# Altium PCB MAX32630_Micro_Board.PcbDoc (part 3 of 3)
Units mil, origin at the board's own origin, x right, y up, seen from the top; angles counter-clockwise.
Board outline 1192.91 x 1079.23 mil, 6 copper layers (Top Layer, Ground Plane +, Mid-Layer 2, Mid-Layer 3, Power Plane 1.8v, Bottom Layer), stack 51.6 mil thick; 105 components, 122 nets, 1109 pads, 512 vias.
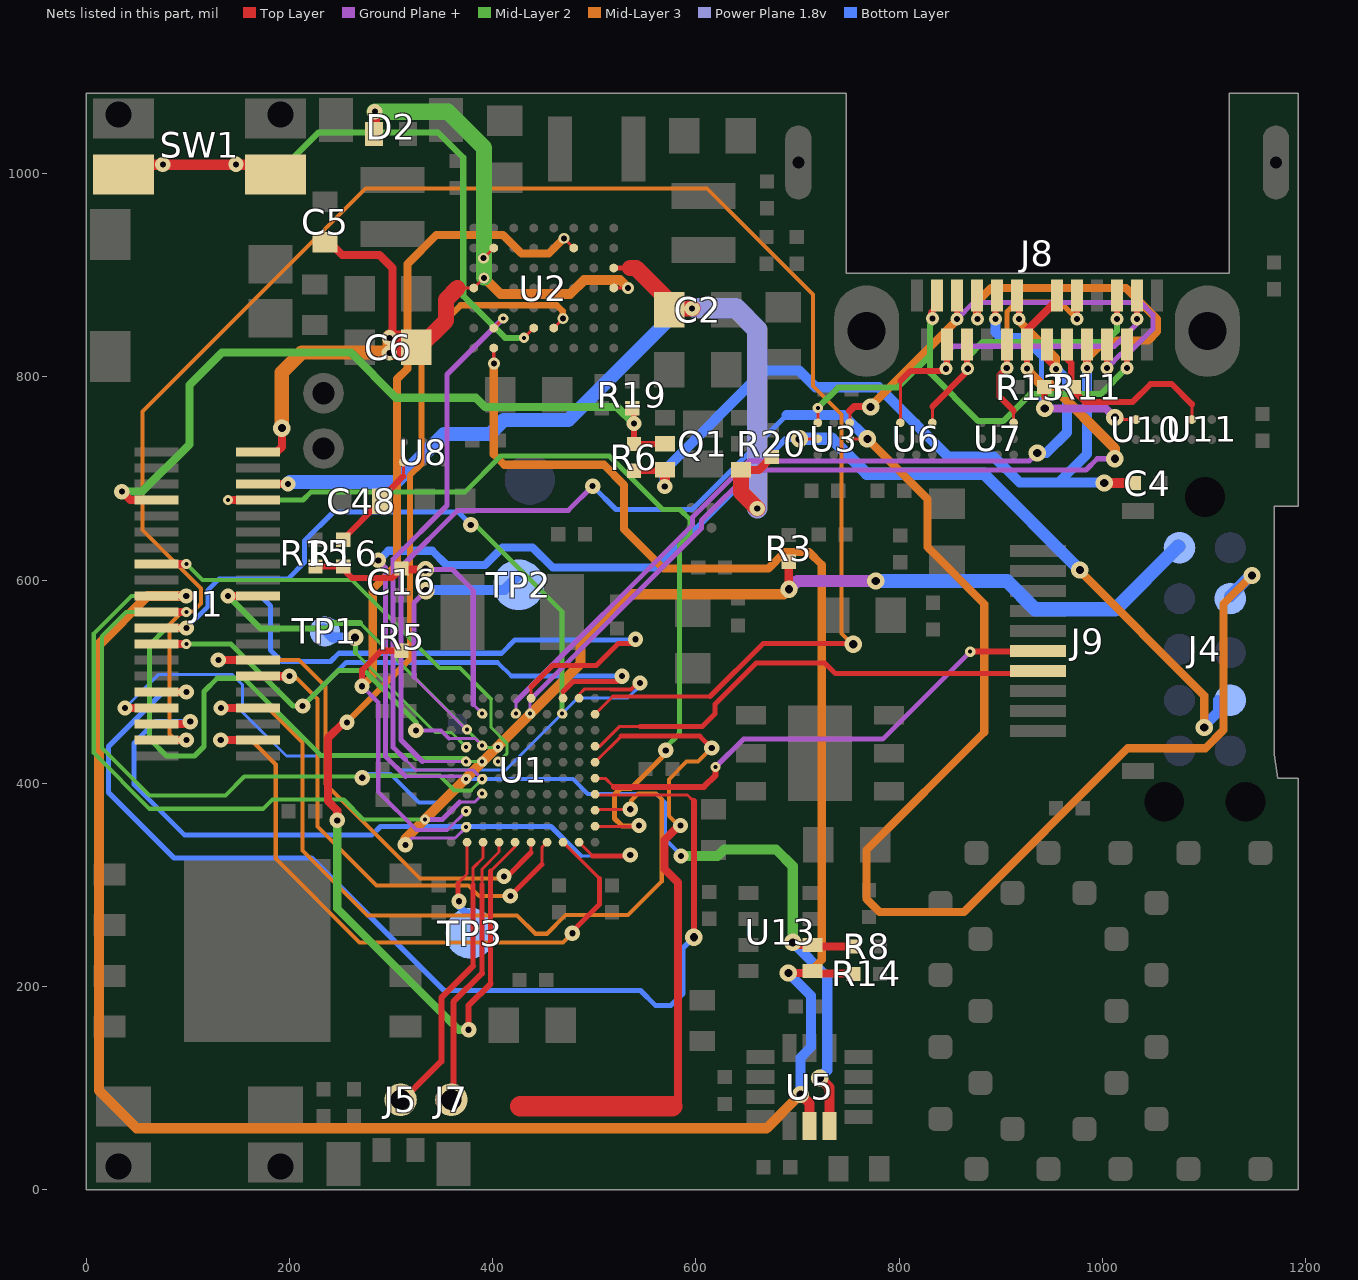
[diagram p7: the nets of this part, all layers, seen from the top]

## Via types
v1: diameter 15, hole 6, Top Layer to Bottom Layer, tented both sides, 180 vias
v2: diameter 10, hole 4, Top Layer to Ground Plane +, tented both sides, 134 vias
v3: diameter 17, hole 8, Top Layer to Bottom Layer, tented both sides, 82 vias
v4: diameter 10, hole 4, Ground Plane + to Mid-Layer 2, tented both sides, 57 vias
v5: diameter 12.8, hole 6, Top Layer to Bottom Layer, tented both sides, 20 vias
v6: diameter 10, hole 4, Top Layer to Ground Plane +, tented top, 16 vias
v7: diameter 10.63, hole 5.91, Top Layer to Bottom Layer, tented both sides, 13 vias
v8: diameter 10, hole 4, Ground Plane + to Mid-Layer 2, 5 vias
v9: diameter 11.81, hole 5.91, Top Layer to Bottom Layer, tented both sides, 3 vias
v10: diameter 14.17, hole 6, Top Layer to Bottom Layer, tented both sides, 1 vias
v11: diameter 14, hole 8, Top Layer to Bottom Layer, tented both sides, 1 vias

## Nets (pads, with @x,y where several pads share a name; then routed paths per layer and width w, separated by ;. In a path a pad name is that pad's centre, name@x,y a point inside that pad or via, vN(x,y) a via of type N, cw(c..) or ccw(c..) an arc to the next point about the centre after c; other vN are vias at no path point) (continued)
P53_SSEL: J1.19 pad.1@405.38,435.51 U1.D7 U1.F10 | length 962.9
  Top Layer w3: U1.F10@437.76,483.65 437.76,494.76 ; v1(540.49,541.74) 542.26,541.74 v1@543,541
  Top Layer w5: 437.76,494.76 459,516 502,516 523.39,537.39 537.39,537.39 540.49,540.49 v1(540.49,541.74)
  Top Layer w8: v1(139.54,584.27) J1.19@169,584.27
  Mid-Layer 2 w3: 269.26,557.89 392.15,435 403.08,435 v4@405.38,437.29
  Mid-Layer 2 w6: v1(139.54,584.27) 171.41,552.39 237.92,552.39 243.42,557.89 269.26,557.89
  Bottom Layer w5: v1(139.54,584.27) 171.73,584.27 181.39,574.61 181.39,530.98 192.48,519.89 240.44,519.89 248.56,528 408.83,528 421.83,541 v1@542,541
  other v2: 405.38,435.51
  other v4: 405.38,435.51
P54_SDIO2: J1.26 U1.C7 U1.H10 | length 803.8
  Top Layer w3: U1.H10@469.25,483.65 469.25,490.25 ; v1@525,502 v1@525,507
  Top Layer w5: 469.25,490.25 479,500 523,500 v1@525,502
  Top Layer w8: J1.26@69,537.02 v4(98.46,537.02)
  Ground Plane + w3: 356.87,444.13 382.8,444.13 v2(389.63,437.29)
  Ground Plane + w4: v1@326.9,452 349,452 356.87,444.13
  Ground Plane + w6: v1@325,453.9 v1@326.9,452
  Mid-Layer 2 w5: v4@98.89,536.89 142.5,536.89 203.39,476 v1(213,476) 248,511 273.5,511 325.05,459.45 v1@325.05,453.95
  Bottom Layer w4: 404.96,519 418.57,505.39
  Bottom Layer w5: v1(213,476) 256,519 404.96,519 ; 418.57,505.39 v1(527.39,505.39)
  other v1: 324.39,451.89
  other v2: 98.46,537.02
P55_SDIO3: J1.24 U1.C6 U1.H9 | length 1182.2
  Top Layer w8: J1.24@69,552.77 v1(98.46,552.77)
  Mid-Layer 2 w3: 373.59,424.39 376.43,421.54 v4(389.63,421.54) ; v1(378.39,654.39) 380.39,654.39 381.39,653.39 v1@380,652
  Mid-Layer 2 w5: v1(98.46,552.77) 78.77,552.77 62.39,536.39 62.39,443.39 78.89,426.89 106.5,426.89 115.89,436.28 115.89,490.39 128.89,503.39 154.89,503.39 230.78,427.5 321.28,427.5 324.39,424.39 373.59,424.39 ; v1(378.39,654.39) 382.89,654.39 468.37,568.91 v2(468.37,468.79)
  Bottom Layer w5: v1(98.46,552.77) 119.95,574.26 119.95,590.37 130.48,600.89 198.21,600.89 214.65,617.33 214.65,638.4 243.26,667 366,667 378.61,654.39 v1(378.39,654.39)
  other v2: 389.63,421.54
  other v4: 468.37,468.79
P56_SRN: J1.16 U1.D6 | length 456.6
  Top Layer w8: J1.16@69,615.76 v8(98.46,615.76)
  Mid-Layer 2 w3: 398.39,483.02 398.39,455.09 414,439.48 414,429 406.54,421.54 v4(405.38,421.54)
  Mid-Layer 2 w4: v8(98.46,615.76) 114.34,599.89 261.39,599.89 347.89,513.39 368.02,513.39 398.39,483.02
  other v2: 405.38,421.54
  other v6: 98.46,615.76
P57_SDA: J1.22 pad.1@389.63,404.02 R8.1 U1.C5 U2.B2 U5.14 U13.3 | length 2079
  Top Layer w3: U2.B2@401.07,848.07 v2@411.24,858.24 ; U13.3@715,240.96 U13.3@716.57,239.39 ; R8.1@753.39,239.39 R8.1@754.39,238.39
  Top Layer w8: J1.22@69,568.52 v4(98.46,568.52) ; v3@697.4,240.96 U13.3@715,240.96 ; U13.3@716.57,239.39 R8.1@753.39,239.39
  Top Layer w10: v3(722,110) 731.68,100.32 U5.14@731.68,62.61
  Ground Plane + w3: 314.11,423.39 325.11,412.39 ; 325.11,412.89 380.76,412.89 v2(389.63,404.02)
  Ground Plane + w5: 314.11,423.39 302.03,435.47 302.03,620.53 355,673.5 355,802.33 v2@411.07,858.41
  Mid-Layer 2 w3: 378.6,393 v2(389.63,404.02)
  Mid-Layer 2 w4: v4(98.46,568.52) 39.02,568.52 15.39,544.89 15.39,434.76 62.26,387.89 136.89,387.89 155.5,406.5 266.72,406.5 268.61,408.39 268.61,402.39 v1(271.61,405.39) 273.61,407.39 348.02,407.39 362.41,393 378.6,393
  Mid-Layer 2 w10: v1(585.39,328.39) 621.39,328.39 627.89,334.89 678.89,334.89 695.39,318.39 v3(695.39,243.39)
  Bottom Layer w4: v1@271.61,405.89 274.95,409.23 299.27,409.23 327.5,381 347,381 370.02,404.02 478.94,404.02 493.58,389.39 561.02,389.39 569.53,380.88 569.53,345.25 582.39,332.39 v1@582.39,328.39
  Bottom Layer w10: v3(695.39,243.39) 729.39,209.39 729.39,117.39 v3(722,110)
  other v2: 98.46,568.52 410.39,857.39
  other v4: 389.63,404.02
P60_SCL: J1.20 R14.1 U1.C4 U2.B1 U5.13 U13.4 | length 3111.9
  Top Layer w3: v9@401.07,813 U2.B1@401.07,828.39 ; U13.4@715,215.37 U13.4@717.02,217.39
  Top Layer w8: J1.20@69,584.27 v1@98.46,584.27 ; v3(691,213.18) U13.4@712.78,213.18 ; U13.4@716.57,212.82 R14.1@753.39,212.82
  Top Layer w10: v3(703,93.78) 712,84.78 U5.13@712,62.61
  Ground Plane + w3: 367.39,381.39 382.03,381.39 389.63,388.98 v2(389.63,390.05)
  Ground Plane + w5: v4(333.39,364.39) 350.39,364.39 367.39,381.39
  Mid-Layer 2 w4: v1(98.39,584.27) 44.38,584.27 7.39,547.28 7.39,429.89 62.39,374.89 174.11,374.89 183.22,384 253.43,384 273.04,364.39 v4(333.39,364.39)
  Mid-Layer 3 w8: v9@401.07,811.48 401.07,723.81 411.39,713.5 509.5,713.5 529.39,693.61 529.39,650 567.89,611.5 671.5,611.5 687.5,627.5 711.5,627.5 723.89,615.11 723.89,226.31 710.76,213.18 v3(691,213.18)
  Mid-Layer 3 w10: v1(98.39,584.27) 60.27,584.27 12.39,536.39 12.39,97.76 49.76,60.39 669.61,60.39 v3(703,93.78)
  Bottom Layer w10: v3(691,213.18) 713.39,190.79 713.39,140.39 703,130 v3(703,93.78)
  other v9: 401.39,813.39
P61_SPI_SCK: J1.34 U1.J10 | length 711.3
  Top Layer w3: U1.J10@485,483.65 485,487.38 490.62,493 516,493 516.61,492.39
  Top Layer w4: 516.61,492.39 536.34,492.39 v1@543.95,500
  Top Layer w8: v1(38.03,474.03) J1.34@69,474.03
  Bottom Layer w3: v1(38.03,474.03) 70.89,506.89 143.93,506.89 153.65,497.17 153.65,470.24 197.01,426.88 294.3,426.88 308.17,413.01 412.86,413.01 483.74,483.89 533,483.89 v1@546.66,497.55
  other v1: 544.89,498.81
P62_SPI_MOSI: J1.38 U1.K9 | length 1847.5
  Top Layer w3: U1.K9@500.75,467.91 518.23,485.39
  Top Layer w4: 518.23,485.39 614.02,485.39
  Top Layer w5: 614.02,485.39 666.02,537.39 752.89,537.39 v3@754.89,539.39
  Top Layer w8: J1.38@69,442.54 v1(98.46,442.54)
  Mid-Layer 3 w4: v1(98.46,442.54) 87.68,442.54 81.89,448.32 81.89,556.39 94.5,569 105,569 112.89,576.89 112.89,591.89 55.39,649.39 55.39,765.89 274.89,985.39 611,985.39 715.39,881 715.39,791 743.39,763 743.39,547.39 v3@754.39,536.39
  other v3: 754.89,536.89
P64_DISP_EXTCOM: J9.4 U1.K7 | length 473.2
  Top Layer w3: U1.K7@500.75,436.41 505.41,436.41 525,456 544.93,456 545.04,455.89
  Top Layer w5: 545.04,455.89 606.39,455.89 618.89,468.39 618.89,477.89 659.39,518.39 726.89,518.39 737.28,508 J9.4@930,508
P65_PUSHBTN: U1.K6 | length 671.2
  Top Layer w3: U1.K6@500.75,420.66 526.48,446.39
  Top Layer w5: 526.48,446.39 603.89,446.39 v1(615.59,434.69)
  Top Layer w8: 582.39,87.39 582.39,302.39 569,315.78 569,344 v1@585,360
  Top Layer w20: 427.2,81.95 576.8,81.95
  Mid-Layer 3 w3: v1@583,358.39 v1(585,358.39)
  Mid-Layer 3 w4: v1@583,358.39 573.39,368 573.39,403.89 590.89,421.39 602.29,421.39 v1(615.59,434.69)
P66_DISP_ON/O\F\F\: J9.5 U1.K5 | length 499.4
  Top Layer w3: U1.K5@500.75,404.91 510.86,404.91 519.39,396.39
  Top Layer w6: 519.39,396.39 607.89,396.39 619.39,407.89 v2(619.39,416) ; v2(870,529.5) J9.5@936.69,529.5
  Ground Plane + w5: v2(619.39,416) 646.78,443.39 783.89,443.39 v2(870,529.5)
P67_SDA: J1.32 U1.K4 | length 1124.3
  Top Layer w3: U1.K4@500.75,389.17 501.41,388.5 591.78,388.5 598,382.28
  Top Layer w6: v3(598,248.39) 598,382.28
  Top Layer w8: J1.32@69,489.78 v1(98.46,489.78)
  Bottom Layer w5: v1(98.46,489.78) 75.59,489.78 21.89,436.08 21.89,390.89 86.39,326.39 221.59,326.39 352.01,195.96 545.57,195.96 560.15,181.39 575.64,181.39 587.39,193.14 587.39,237.78 v3(598,248.39)
P70_SCL: J1.33 U1.K3 | length 811.1
  Top Layer w3: U1.K3@500.75,373.42 501.17,373 502.55,374.39 v1@536.39,374.39
  Top Layer w8: v1(132.53,474.03) J1.33@169,474.03
  Ground Plane + w4: v1@536.39,374.39 v1@540.57,374.39
  Mid-Layer 3 w4: v1(132.53,474.03) 178.97,474.03 213,440 213,333.89 277,269.89 424.11,269.89 442.11,251.89 453.39,251.89 471.89,270.39 533.39,270.39 566.39,303.39 566.39,384.39 560.89,389.89 543.28,389.89 536.39,383 v1@536.39,374.39
  other v1: 535.39,374.39
P71_SDA: J1.7 U1.K2 | length 927.8
  Top Layer w3: U1.K2@500.75,357.67 v1@543.95,357.67
  Top Layer w8: v4(139.54,678.76) J1.7@169,678.76
  Mid-Layer 2 w5: v4(139.54,678.76) 213.26,678.76 221,686.5 372.5,686.5 408,722 514.78,722 567.39,669.39 584.39,669.39 594.39,659.39 594.39,644.39 584,634 584,449 v1@569,434
  Mid-Layer 3 w5: v1(543.95,358.45) 543.58,358.08 527.2,358.08 519.89,365.39 519.89,388.89 525.89,394.89 535.96,394.89 569,427.93 v1@569,432.39
  other v1: 570.39,432.39
  other v2: 139.54,678.76
P72_SCL: J1.36 U1.J1 | length 718.4
  Top Layer w3: U1.J1@485,341.92 498.53,328.39 ; v1@532.86,328.39 v1@533.25,328
  Top Layer w5: 498.53,328.39 v1@532.86,328.39
  Top Layer w8: J1.36@69,458.28 100.04,458.28 v1(102.39,460.64)
  Bottom Layer w3: 486.54,328.46 v1@534.46,328.46
  Bottom Layer w5: v1(102.39,460.64) 68.14,460.64 46.81,439.31 46.81,398.97 96.89,348.89 280.97,348.89 289.55,357.47 457.53,357.47 486.54,328.46 ; v1@534.46,328.46 v1(535.39,329.39)
P73_SCK: J1.37 U1.H1 | length 640.3
  Top Layer w3: U1.H1@469.25,341.92 469.47,341.92 505,306.39 ; v1@480.4,251.99 v1@480.4,256.13
  Top Layer w5: v1@480.4,256.13 505,280.73 505,306.39
  Top Layer w8: v1(132.39,442.54) J1.37@169,442.54
  Mid-Layer 3 w4: v1(132.39,442.54) 162.39,442.54 186.5,418.42 186.5,326 269.11,243.39 469.39,243.39 v1@480,254
  other v1: 478.39,252.39
P74_MOSI: J1.29 U1.G1 | length 479.3
  Top Layer w3: 448.39,320 448.39,336.81 U1.G1@453.5,341.92
  Top Layer w5: v1(417.39,289) 448.39,320
  Top Layer w8: J1.29@169.14,505.39 v1(199.89,505.39)
  Mid-Layer 3 w4: v1(199.89,505.39) 205.11,505.39 227.39,483.11 227.39,357.61 285.61,299.39 376.39,299.39 386.78,289 v1(417.39,289)
P75_MISO: J1.27 U1.F1 | length 512.5
  Top Layer w3: v1@411,309 v1@415,309 ; 437.76,331.76 U1.F1@437.76,341.92
  Top Layer w5: v1@415,309 437.76,331.76
  Top Layer w8: v1(130,521.28) J1.27@169,521.28
  Ground Plane + w3: v1@410.39,308.39 v1@411,309
  Mid-Layer 3 w4: v1(130,521.28) 209.22,521.28 235.39,495.11 235.39,399.39 328.39,306.39 408.39,306.39 v1@410.39,308.39
  other v1: 411.04,308.39
P76_PMIC_PFN2: U1.E1 U2.E2 | length 1161.2
  Top Layer w3: 397.89,313.39 422.01,337.51 U1.E1@422.01,341.92 ; U2.E2@460.13,848.07 v7@470.3,858.24
  Top Layer w5: 397.89,202.89 397.89,313.39
  Top Layer w6: v1(376.39,157.39) 376.39,181.39 397.89,202.89
  Top Layer w8: v1(247,363.5) 247,373.28 237.89,382.39 237.89,444.51 253.38,460 v1(256.5,460)
  Mid-Layer 2 w8: v1(247,363.5) 247,276.78 366.39,157.39 v1(376.39,157.39)
  Mid-Layer 3 w6: v1(256.5,460) 318.5,522 318.5,703 330,714.5 330,832 368.5,870.5 463.17,870.5 469,864.67 469,857.28 v7@469.59,857.87
  other v7: 469.19,857.39
P77_SDA: J7.1 U1.D1 | length 291.9
  Top Layer w3: 389.5,300.28 389.5,315.5 406.26,332.26 ; 389.63,315.63 406.26,332.26 ; U1.D1@406.26,341.92 406.26,332.26
  Top Layer w5: 389.5,213 389.5,300.28
  Top Layer w6: J7.1@355.93,94.39 361.39,99.85 361.39,184.89 389.5,213
P80_SCL: J5.1 U1.C1 | length 301.9
  Top Layer w3: 380.5,300.28 380.5,316.5 390.51,326.51 ; 381,317 390.51,326.51 ; U1.C1@390.51,341.92 390.51,326.51
  Top Layer w5: 380.5,220 380.5,300.28
  Top Layer w6: J5.1@307.76,92.39 315.64,92.39 349.53,126.28 349.53,189.03 380.5,220
P81: TP3.1 U1.B1 | length 80.1
  Top Layer w3: 366,301.89 374.76,310.65 U1.B1@374.76,341.92
  Top Layer w5: v1@364.39,283.39 366,285 366,301.89
  Bottom Layer w5: v1@364.39,281.44 v1@364.39,283.39 ; TP3.1@372.44,273.39 TP3.1@376.39,273.39
  Bottom Layer w7: v1@364.39,281.44 TP3.1@372.44,273.39
  other v1: 366.89,283.89
PMIC_PFN1: SW1.1 SW1.2 U2.D2 | length 602.7
  Top Layer w3: v2@430.28,837.91 v4(430.81,838.44) U2.D2@440.44,848.07
  Top Layer w6: SW1.2@60.39,1009 v1(75.39,1009) v1@76,1009
  Top Layer w10: SW1.2@50.39,1008.78 SW1.1@163.39,1008.78
  Mid-Layer 2 w6: v1(147.39,1009.17) 197.17,1009.17 228.39,1040.39 346.39,1040.39 371,1015.78 371,879.78 412.33,838.44 v4(430.81,838.44)
  other v2: 430.81,838.44
RSENSE1: J8.B5 R13.1 U10.A2 | length 288.9
  Top Layer w3: v3@1007,758 U10.A2@1033.31,758 ; v3(1012.39,760) v3@1012.39,763.07
  Top Layer w6: v5(894.89,856.89) 894.89,878.74 J8.B5@896.36,880.21 ; R13.1@943,790 943,772 v3@947,768
  Top Layer w8: v3(943.39,769) v3@946.78,769 ; v3(1012.39,760) v3@1016.81,760
  Ground Plane + w3: v3(1012.39,760) v3@1012.39,764.64
  Ground Plane + w8: v3(943.39,769) 1003.39,769 v3(1012.39,760)
  Bottom Layer w5: v5(894.89,856.89) 897.46,856.89 v5@897.57,857 ; 940.39,822.41 940.39,773.61 v3@946,768
  Bottom Layer w10: v5(894.89,856.89) 894.89,844.05 900.66,838.28 924.52,838.28 940.39,822.41
RSENSE2: J8.A5 R11.1 U11.A2 | length 200
  Top Layer w3: R11.1@969.5,792.5 R11.1@972,790 ; U11.A2@1088.16,758 1088.16,773.08
  Top Layer w6: J8.A5@965.26,831.97 965.26,817.74 969.5,813.5 R11.1@969.5,792.5 ; R11.1@972,790 972,786 982.69,775.31 1029.93,775.31 1047.62,793 1068.24,793 1088.16,773.08
RST_N: R5.1 U1.B3 U2.F6 | length 918.1
  Top Layer w3: v7(470.24,936.39) U2.F6@479.81,926.81
  Top Layer w6: v1(271.39,495.5) 271.39,511.39 290.39,530.39 R5.1@310.39,530.39
  Ground Plane + w3: 355.14,353.79 v2(373.88,372.52)
  Ground Plane + w4: v1(271.39,495.5) 287.39,479.5 287.39,391.58 325.18,353.79 355.14,353.79
  Ground Plane + w5: v1@269.28,495.5 v1(271.39,495.5)
  Mid-Layer 3 w8: v1(271.39,495.5) 282,506.11 282,591 306,615 306,798 315.99,807.99 315.99,910.99 344.5,939.5 410.28,939.5 428.39,921.39 455.24,921.39 v7(470.24,936.39)
  Bottom Layer w5: v1(271.39,495.5) 269.28,495.5 v1@271.67,497.89
RX1RX+_HDK_RX: J8.A11 J8.B11 U6.C3 | length 360.2
  Top Layer w3: U6.C3@801.25,754.75 801.25,795.75
  Top Layer w6: 801.25,795.75 811.31,805.81 847.15,805.81 J8.A11@847.15,831.97 ; v5(1034.16,857) J8.B11@1034.16,880.21
  Ground Plane + w3: v5@1034.16,852.32 v5(1034.16,857)
  Ground Plane + w5: v5(846,808) 846,822.65 853.47,830.12 1011.95,830.12 v5@1034.16,852.32
RX1RX-_HDK_TX: J8.A10 J8.B10 U6.C1 | length 295.7
  Top Layer w3: U6.C1@832.75,754.75 832.75,770.75
  Top Layer w6: 832.75,770.75 866.83,804.83 J8.A10@866.83,831.97 ; v5(1014.47,857) J8.B10@1014.47,880.21
  Mid-Layer 2 w6: v5@867,808 867,819 882.39,834.39 1003.63,834.39 1014.47,845.23 v5(1014.47,857)
  other v5: 867.59,808
S\R\S\T\: J4.10 pad.1@373.88,356.77 R3.2 U1.B2 | length 1006.5
  Top Layer w8: 691.39,599.7 R3.2@691.39,618
  Ground Plane + w3: v1(314.06,339.4) 320.97,346.3 363.41,346.3 v4(373.88,356.77)
  Ground Plane + w12: v3(691.71,591) 699.71,599 v3(777,599)
  Mid-Layer 3 w10: v1@314.44,339.02 314.44,345.6 486.39,517.55 486.39,538.39 534,586 686.71,586 v3(691.71,591)
  Bottom Layer w14: v3(777,599) 906.16,599 933.99,571.17 1012.71,571.17 J4.10@1074.68,633.14
  other v2: 373.88,356.77
SBU_VREF: J8.A8 J8.B8 U7.C1 | length 244.7
  Top Layer w3: U7.C1@912.75,754.75 912.75,766.57
  Top Layer w6: J8.A8@906.2,831.97 906.2,809.2 899,802 899,780.31 912.75,766.57 ; v5(975.1,857) J8.B8@975.1,880.21
  Ground Plane + w3: v5(906,808.76) 905.76,808.76 v5@906,809
  Mid-Layer 3 w3: v5@906,809 v5@906.39,809.39
  Mid-Layer 3 w5: v5@906.39,809.39 906.39,864.39 915.68,873.68 958.43,873.68 v5(975.1,857)
SYS_OUT: C5.1 C6.1 D2.2 J1.1 U2.A4 U2.B6 U2.H4 | length 991.7
  Top Layer w3: C6.1@312.56,828.39 C6.1@321.33,828.39 ; 365.44,887.44 U2.A4@381.39,887.44 v7@391.55,897.61 ; v7@391.44,917.18 U2.B6@401.07,926.81 ; U2.H4@519.18,887.44 v9@532.39,887.44
  Top Layer w8: J1.1@169,726 187.5,726 192.5,731 v3(192.5,749.5) ; C5.1@240,932 252,920 288.5,920 301.5,907 301.5,839.44 C6.1@312.56,828.39
  Top Layer w10: D2.2@284.01,1039.22 v1(284.01,1061)
  Top Layer w14: v1(298.29,823.39) 309.23,823.39 ; v1(298.45,838.44) 309.39,838.44
  Top Layer w16: C6.1@324.17,825.55 354,855.39 354,876 365.44,887.44
  Mid-Layer 2 w16: v1(284.01,1061) 355.99,1061 391.41,1025.59 v7@391.41,897.76
  Mid-Layer 3 w10: v7@391.41,897.76 407.66,881.5 476.11,881.5 490,895.39 525.25,895.39 v9(533.25,887.39)
  Mid-Layer 3 w14: v3(192.5,749.5) 192.5,804.39 212.02,823.91 298.41,823.91 298.45,823.95 v1@298.45,839.39 ; v1@299.23,826.39 v1@299.23,838.44
  other v7: 391.39,897.39 391.02,916.76
TCK/SWCLK: J4.4 U1.B5 U3.B3 | length 1363
  Top Layer w3: v3@701.61,739 v3(702,739) U3.B3@720,739
  Ground Plane + w3: 314.11,406.89 371.01,406.89 v2(373.88,404.02)
  Ground Plane + w5: v1(287.39,619.39) 294.39,612.39 294.39,426.61 314.11,406.89
  Mid-Layer 3 w8: v3(977.92,610) 977.92,608.97 1100.32,486.57 v3(1100.32,455)
  Bottom Layer w6: 561.85,612.39 688.46,739 v3(702,739)
  Bottom Layer w8: v1(287.39,619.39) 287.78,619.39 297.29,628.9 340.53,628.9 354.43,615 392.36,615 409.52,632.16 439.34,632.16 459.1,612.39 561.85,612.39
  Bottom Layer w10: v3@1099.5,455 1099.5,455.75 1114,470.25 J4.4@1114,482
  Bottom Layer w12: v3(702,739) 733.78,739 768.19,704.59 883.33,704.59 v3(977.92,610)
  other v4: 373.88,404.02
TDI: TP2.1 U1.B8 | length 263.9
  Ground Plane + w3: 322.39,504.53 v6@374.76,452.16
  Ground Plane + w5: 322.39,504.53 322.39,577.39 v3(334.39,589.39)
  Bottom Layer w10: v3(334.39,589.39) 335.39,590.39 411.39,590.39 TP2.1@427.39,606.39
  other v6: 374.76,453.04
TDO: TP1.1 U1.B7 | length 197
  Mid-Layer 2 w3: 265,528.44 343.44,450 359.39,450 v2(373.88,435.51)
  Mid-Layer 2 w5: 265,528.44 v3@265,543.39
  Bottom Layer w10: TP1.1@233.5,552.44 242.55,543.39 v3(264.39,543.39)
  other v4: 373.88,435.51
TMS/SWDIO: J4.2 U1.B6 U3.B1 | length 1982.5
  Top Layer w3: U3.B1@751.5,739 v3(768.75,739)
  Ground Plane + w3: 330.84,421.54 v6(373.89,421.54)
  Ground Plane + w5: 330.84,421.54 309.89,442.49 309.89,612.89 365.64,668.64 474.48,668.64 v1@498.31,692.47
  Mid-Layer 3 w8: v3(768.75,739) 828,679.75 828,632.5 883.88,576.62 883.88,450.21 768.02,334.35 768.02,286.08 780.71,273.39 863.91,273.39 1025.02,434.5 1101.5,434.5 1119.5,452.5 1119.5,576.65 v3(1147.39,604.54)
  Bottom Layer w5: v1(498.39,692.39) 521.32,669.46 596.46,669.46 689.39,762.39
  Bottom Layer w10: 689.39,762.39 745.36,762.39 v3(768.75,739)
  Bottom Layer w12: J4.2@1125.66,584.16 1145.67,604.17 v3@1147.02,604.17
TX1TX+_SWDCLK: J8.A2 J8.B2 U3.C3 | length 495
  Top Layer w3: U3.C3@720,754.75 v2(720,769.39)
  Top Layer w6: v5@836.39,857.39 831.39,862.39 831.39,862.89 837.31,868.81 J8.B2@837.31,880.21 ; v5(1024.31,808.76) J8.A2@1024.31,831.97
  Mid-Layer 2 w3: v5@836,857 v5@836,858
  Mid-Layer 2 w6: v2(720,769.39) 740,789.39 798.39,789.39 830.5,821.5 830.5,827.69 ; v5@836,857 830.5,851.5 830.5,803.89 878,756.39 902.39,756.39 929,783 998.56,783 v5(1024.31,808.76)
  other v4: 720,769.39
  other v5: 832.89,857.39
TX1TX-_SWDIO: J8.A3 J8.B3 U3.C1 | length 481.5
  Top Layer w3: U3.C1@751.5,754.75 751.5,766.5
  Top Layer w6: v5(856.99,857) J8.B3@856.99,880.21 ; v5(1004.63,808.76) J8.A3@1004.63,831.97
  Top Layer w7: 751.5,766.5 756,771 v3@772,771
  Ground Plane + w5: v5(856.99,857) 873.38,873.39 1037.55,873.39 1049.81,861.13 1049.81,847.16 1025.29,822.65 1018.52,822.65 v5(1004.63,808.76)
  Mid-Layer 3 w3: v5@856.99,855.99 v5(856.99,857)
  Mid-Layer 3 w8: v3@772,771 v5@856.99,855.99
  other v3: 772,770.39
"USB DM": J8.A7 J8.B7 U1.F9 | length 907.9
  Top Layer w3: J8.A7@925.89,831.97 J8.A7@925.89,845.89 ; J8.B7@952.43,872.43 955.42,872.43 J8.B7@955.42,880.21
  Top Layer w6: v5(925.89,808.39) J8.A7@925.89,831.97
  Top Layer w8: J8.A7@925.89,845.89 J8.B7@952.43,872.43
  Ground Plane + w3: v2(436.87,468.79) 436.87,482.25
  Ground Plane + w5: 436.87,482.25 605.63,651.01 605.63,658.58 655.44,708.39 984.04,708.39 995.04,719.39 v3(1012.39,719.39)
  Mid-Layer 3 w10: v5(925.89,808.39) 925.89,806.48 940.37,792 950,792 1012.39,729.61 v3(1012.39,719.39)
"USB DP": J8.A6 J8.B6 U1.E9 | length 855.1
  Top Layer w6: J8.B6@916.05,880.21 917.89,878.37 v5(917.89,856.86) ; J8.A6@945.57,831.97 944.89,831.28 944.89,817.89 954.39,808.39 v5(954.39,807.89)
  Ground Plane + w3: v2(422.91,468.79) 422.91,480.39
  Ground Plane + w5: 422.91,480.39 596.52,654 596.52,661.65 651.98,717.11 928.11,717.11 v3(936,725)
  Mid-Layer 3 w5: v5@917.89,855.16 v5(917.89,856.86)
  Mid-Layer 3 w8: v5@917.89,855.16 954.39,818.66 v5(954.39,807.89)
  Bottom Layer w10: v3(936,725) 945,725 965.39,745.39 965.39,796.89 953.72,808.56 953.06,807.89 v5(954.39,807.89)
USB_VBUS: C4.1 J8.A4 J8.B4 Q1.3 R6.2 | length 1096.2
  Top Layer w6: R6.2@539,707.61 Q1.3@568.8,707.61 ; v5@876.68,857 J8.B4@876.68,880.21 ; v5(984.94,808.76) J8.A4@984.94,831.97
  Top Layer w10: v1@569.6,691.21 Q1.3@569.6,708.41 ; v3(1002,695.5) C4.1@1031,695.5
  Mid-Layer 3 w8: v5@876.68,857 876.68,873.68 890.39,887.39 1023.47,887.39 1054,856.86 1054,844.5 1045.39,835.89 1002.89,835.89 984.94,817.94 v5(984.94,808.76)
  Bottom Layer w10: v1(569.39,692) 569.39,708.39 667.39,806.39 701.39,806.39 718.07,789.71 780.07,789.71 848.28,721.5 893.28,721.5 918.78,696 957,696 ; v5(984.94,808.76) 984.94,723.94 957,696 ; v3(1002,695.5) 1001.5,696 957,696
  other v5: 877.18,857
V_CHGIN: C2.1 J1.5 Q1.4 R20.2 U2.H5 | length 911
  Top Layer w5: U2.H5@519.18,907.13 536.76,907.13
  Top Layer w8: J1.5@169,694.5 v1(198.46,694.5) ; Q1.4@644.4,708.41 662.02,708.41 R20.2@674.61,721
  Top Layer w16: 535.39,907.12 541.1,907.12 C2.1@573.51,874.7 ; C2.1@575.39,867.39 v1(596.39,867.39) ; Q1.4@644.4,706.39 644.4,686.38 v1(660.39,670.39)
  Power Plane 1.8v w20: v1@600.39,867.39 639.57,867.39 660.39,846.57 v1(660.39,670.39)
  Bottom Layer w14: v1(198.46,694.5) 200.45,696.49 304.99,696.49 352.39,743.89 397.39,743.89 411,757.5 474.5,757.5 516,799 584.39,867.39 v1@595.39,867.39
VRTC: C16.1 R15.2 R16.2 U1.C9 | length 300.2
  Top Layer w3: C16.1@310.39,611.39 C16.1@311.39,610.39
  Top Layer w6: R15.2@222.5,613.31 250.5,613.31 261.81,602 301,602 C16.1@310.39,611.39
  Top Layer w8: C16.1@311.39,610.39 v3(334,610.39)
  Ground Plane + w3: 380.89,477.53 v6(389.63,468.79)
  Ground Plane + w5: v3@334.39,610.39 360.43,610.39 380.89,589.93 380.89,477.53
  other v8: 389.63,468.79
VRTC_LDO: C48.1 R16.1 U8.B1 | length 100.2
  Top Layer w3: C48.1@290,677.5 C48.1@291,677.5 ; 312.16,702.05 U8.B1@312.16,716.16
  Top Layer w6: R16.1@250.5,639.69 252.19,639.69 C48.1@290,677.5 ; C48.1@291,680.89 312.16,702.05
WCP_DIS: J1.8 Q1.2 R6.1 R19.2 | length 727
  Top Layer w6: R19.2@539,769 R6.1@539,734 Q1.2@569.6,734
  Top Layer w8: v1(35,687) 43.24,678.76 J1.8@69,678.76
  Mid-Layer 2 w8: v1(35,687) 55,687 101.5,733.5 101.5,792 133.5,824 260.39,824 305,779.39 383.61,779.39 392.5,770.5 522.5,770.5 v1(539,754)
pads on no net: J2.0 J4.0 J4.5 J4.7 J9. MOD1.2 MOD1.7 MOD1.9 MOD1.13 MOD1.17 MOD1.18 MOD1.19 MOD1.21 MOD1.23 MOD1.24 MOD1.A MOD1.B MOD1.C MOD1.D Q1.7 Q1.8 U1. U1.A1 U1.A10 U1.K1 U1.K10 U2. U2.B3 U2.B4 U2.B5 U2.C3 U2.C4 U2.C5 U2.F1 U2.H1 U2.H2 U3. U3.A1 U3.A3 U5.2 U5.3 U5.9 U5.10 U5.11 U6. U6.A1 U6.A3 U7. U7.A1 U7.A3 U8.B3 U10. U11. U12.3 U12.4 U12.5 U12.6
copper on no net: | length 110.9
  Top Layer w20: v1(18.5,783.5) 18.5,820 v1(18.5,856.5) ; v1(18.5,903.5) 18.5,940
  Bottom Layer w3: 598,539 599,540

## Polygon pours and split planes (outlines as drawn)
1V8 on Power Plane 1.8v "PP_1V8" (solid, remove dead copper, pour order 24): -4.61,-3.61 -4.61,1081.39 1194.39,1081.39 1194.39,1.48 1192.91,0
BAT on Power Plane 1.8v "BAT" (solid, remove dead copper, pour order 20): 49.12,876.77 80.93,844.97 158.1,844.99 175.5,862.39 275.14,862.39 356.14,943.39 502.18,943.39 505.39,940.18 505.39,862.39 522.81,844.97 549.25,844.97 564.12,859.85 564.12,978.65 534.39,1008.39 272.39,1008.39 228.39,964.39 86.56,964.39 69.01,964.39 49.12,944.5
3V on Power Plane 1.8v "POWERPLANE_3V3" (solid, remove dead copper, pour order 18): 703.73,602.5 894.28,602.5 894.28,510.6 748.6,510.6 659.39,421.39 659.39,299.39 547.39,187.39 343.13,187.39 291.39,239.13 291.39,285.78 291.39,329.39 327.44,365.44 374.39,412.39 374.39,599.9 320.9,653.39 78.39,653.39 26.28,705.5 26.28,742.49 37.47,753.68 72.32,753.68 164.43,753.68 364.75,954 434.82,954 476.33,912.5 476.33,294.91 482.23,289 567,289 609.45,331.45 609.45,447.45 677.39,515.39 703.73,541.73
3V3_SFO on Power Plane 1.8v "POWERPLANE_VBUS" (solid, remove dead copper, pour order 16): 672.79,670.77 676.5,667.08 1104.65,666.46 1189,745.74 1189,872 1173.5,887.5 693.25,887.5 672.79,864.96
GND on Ground Plane + "'" (solid, remove dead copper, pour order 22): -4.61,-3.61 -4.61,1080.39 1191.75,1080.39 1192.91,1079.23 1192.91,0
GND on Bottom Layer "BOT_GND" (solid, remove dead copper, pour order 26): -4.61,-3.61 -4.61,1081.39 1192.91,1081.39 1192.91,0

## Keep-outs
Keep-Out Layer:
  lines w1: 0,0 1192.91,0 1192.91,405 1172.5,405 1169.5,428.73 1169.5,672.5 1192.91,672.5 1192.91,1079.23 1125,1079.23 1125,902.22 748,902.22 748,1079.23 0,1079.23 0,0 ; 752.39,907.39 752.39,1079.23 1119.39,1079.23 1119.39,907.39 752.39,907.39
Mechanical 11:
  the board outline again, w1

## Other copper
Top Layer:
  pour cut-out: 1192.91,0 1060.39,0 1060.39,359.39 1192.91,359.39
  text "Top Layer" at 1727,266.55 h25
Ground Plane +:
  pour cut-out: 1192.91,0 1065.39,0 1065.39,386.39 1192.91,386.39
  text "Ground Plane +" at 1727,224.16 h25
Mid-Layer 2:
  text "Mid-Layer 2" at 1727,181.76 h25
Mid-Layer 3:
  pour cut-out: 1192.91,0 1066.39,0 1066.39,386.43 1192.91,386.43
  text "Mid-Layer 3" at 1727,139.36 h25
Power Plane 1.8v:
  pour cut-out: 1192.91,0 1065.39,0 1065.39,386.39 1192.91,386.39
  text "Power Plane 1.8v +" at 1727,96.97 h25
Bottom Layer:
  pour cut-out: 1192.91,0 1065.39,0 1065.39,386 1192.91,386
  text "Bottom Layer" at 1727,54.57 h25

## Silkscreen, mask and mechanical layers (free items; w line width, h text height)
Top Overlay:
  circle w10: c199,760 r4.95
  circle w20: c24,367.5 r8
  rectangle: 356.5,804.5 365,830.5
  rectangle: 356.5,793.5 383.4,813
  rectangle: 558.39,771.24 586.5,779
  rectangle: 334,327.5 341.5,364.39
  rectangle: 345.5,319 366.5,326.5
  rectangle: 144,769 181,788.5
  rectangle: 168.5,735 181,773
  lines w10: 225.5,542.5 225.5,531 251,531 251,542.5
  text "BT-" at 96,925 h40
  text "+" at 211,815 h40 r90
  text "BT+" at 94.5,811.5 h40
  text "-" at 69,787.89 h40
  text "HP+" at 263.39,772.99 h40
  text "2" at 39,717 h40 r90
  text "HP-" at 287.39,703 h40 r90
  text "40" at 39,407.89 h40 r90
  text "Top Silkscreen" at 1727,349.5 h25
Bottom Overlay:
  drawing of 1573 lines, arcs and shapes, not listed
  text "HP+" at 284,830.5 h40 r90
  text "MAX32630 Micro Board" at 895.5,814 h80 r90
  text "HP-" at 286,747 h40 r90
  text "REV A" at 1143.5,276.5 h70 r90
  text "TM" at 648.89,240 h25 r90
  text "P77" at 376.39,178 h40 r90
  text "P80" at 324,177.5 h40 r90
  text "Bottom  Silkscreen" at 1726,-33 h25
Top Solder:
  text "SILKSCREEN: WHITE" at 2220.5,349.5 h25
  text "Top Solder" at 1727,307.5 h25
  text "SOLDERMASK: BLACK or GREEN" at 2096,307 h25
  text "SILKSCREEN: WHITE" at 2240.5,-34 h25
Bottom Solder:
  text "Bottom Solder" at 1721.5,13 h25
  text "SOLDERMASK: BLACK or GREEN" at 2085,12.5 h25
Mechanical 16:
  circle w25: c7712.68,-100.1 r158.12
  lines w5: -1405,1144 -1205,1144 ; -1397,3759 -1197,3759 ; -1397,6134 -1197,6134 ; 1095,-1231 1095,-1031 ; 1095,8069 1095,8269 ; 3595,-1231 3595,-1031 ; 3595,8069 3595,8269 ; 6095,-1231 6095,-1031 ; 6095,8069 6095,8269 ; 8595,-1231 8595,-1031 ; 8595,8069 8595,8269 ; 8895,-731 13395,-731 ; 8895,-431 13395,-431 ; 8895,-131 10395,-131 ; 10395,-1031 10395,-431 10395,169 ; 11095,-1231 11095,-1031 ; 11095,8069 11095,8269 ; 12495,-1031 12495,-431 ; 13395,1144 13595,1144 ; 13395,3519 13595,3519 ; 13395,5894 13595,5894 ; 8895,-1031 8895,169 ; 8895,-1031 13395,-1031 ; 8895,-1031 7495,-1031 7495,169 8895,169 ; 8895,169 10395,169 ; 10395,169 13395,169 13395,-1031 ; 13395,-1031 -1205,-1031 -1205,8069 13395,8069 13395,-1031 ; -1405,-1231 13595,-1231 13595,8269 -1405,8269 -1405,-1231
  text "1" at -173.66,8139 h70
  text "2" at 2322,8139 h70
  text "3" at 4811.34,8139 h70
  text "4" at 7318.01,8139 h70
  text "5" at 9817,8139 h70
  text "6" at 12322,8139 h70
  text "A" at -1330,6996 h70
  text "A" at 13470,6996 h70
  text "B" at -1322,4856 h70
  text "B" at 13470,4616 h70
  text "C" at -1330,2241 h70
  text "C" at 13470,2241 h70
  text "ENGINEER:" at 8945,69 h45
  text "TITLE:" at 10445,69 h45
  text "maxim" at 7927.69,-63.27 h225
  text "MAX32630 Micro Board" at 10544,-81 h118.11
  text "D" at -1330,-129 h70
  text "D" at 13470,-129 h70
  text "T" at 8717.69,-213.27 h100
  text "M" at 8767.69,-213.27 h100
  text "integrated" at 7927.69,-223.27 h225
  text "PCB DESIGNER:" at 8945,-226 h45
  text "Maxim Integrated" at 7602.69,-438.27 h80
  text "DATE:" at 8945,-531 h45
  text "PART NO.:" at 10445,-531 h45
  text "REV:" at 12545,-531 h45
  text "160 Rio Robles" at 7602.69,-593.27 h80
  text "A" at 12721,-634 h59.06
  text "4/5/2018" at 8976,-648 h59.06
  text "San Jose, CA 95134" at 7602.69,-708.27 h80
  text "FILE NAME:" at 8945,-831 h45
  text "DWG NO:" at 10445,-831 h45
  text "SCALE:" at 12545,-831 h45
  text "(408) 733-7600" at 7597.69,-853.27 h80
  text "MAX32630HSP3" at 8995,-951 h59.06
  text "1" at -173.66,-1161 h70
  text "2" at 2322,-1161 h70
  text "3" at 4811.34,-1161 h70
  text "4" at 7318.01,-1161 h70
  text "5" at 9817,-1161 h70
  text "6" at 12322,-1161 h70
Drill Drawing:
  circle w8: c-757.09,5429.64 r12.41
  circle w8: c-757.09,5429.64 r20.69
  circle w8: c-757.09,4871.14 r20.69
  lines w8: -777.77,4674.62 -767.43,4674.62 -757.09,4664.28 -746.75,4674.62 -736.4,4674.62 -746.75,4684.97 -736.4,4695.31 -746.75,4695.31 -757.09,4705.65 -767.43,4695.31 -777.77,4695.31 -767.43,4684.97 -777.77,4674.62 ; -777.77,4778.05 -757.09,4757.37 -736.4,4778.05 -757.09,4798.74 -777.77,4778.05 ; -777.77,4953.88 -767.43,4953.88 -757.09,4943.53 -746.75,4953.88 -736.4,4953.88 -746.75,4964.22 -736.4,4974.56 -746.75,4974.56 -757.09,4984.91 -767.43,4974.56 -777.77,4974.56 -767.43,4964.22 -777.77,4953.88 ; -777.77,5036.62 -757.09,5046.96 -736.4,5036.62 -746.75,5057.3 -736.4,5077.99 -757.09,5067.65 -777.77,5077.99 -767.43,5057.3 -777.77,5036.62 ; -777.77,5171.07 -736.4,5171.07 -757.09,5129.7 -777.77,5171.07 ; -777.77,5222.79 -777.77,5233.13 -767.43,5243.47 -777.77,5253.82 -777.77,5264.16 -767.43,5264.16 -757.09,5253.82 -746.75,5264.16 -736.4,5264.16 -736.4,5253.82 -746.75,5243.47 -736.4,5233.13 -736.4,5222.79 -746.75,5222.79 -757.09,5233.13 -767.43,5222.79 -777.77,5222.79 ; -777.77,5357.24 -736.4,5357.24 -757.09,5315.87 -777.77,5357.24 ; -769.5,4958.01 -763.3,4958.01 -757.09,4951.81 -750.88,4958.01 -744.68,4958.01 -750.88,4964.22 -744.68,4970.43 -750.88,4970.43 -757.09,4976.63 -763.3,4970.43 -769.5,4970.43 -763.3,4964.22 -769.5,4958.01 ; -769.5,5044.89 -757.09,5051.1 -744.68,5044.89 -750.88,5057.3 -744.68,5069.72 -757.09,5063.51 -769.5,5069.72 -763.3,5057.3 -769.5,5044.89 ; -769.5,5162.8 -744.68,5162.8 -757.09,5137.98 -769.5,5162.8
  lines w15: -815.44,4636.36 6801.06,4636.36 ; -815.44,5474.12 6801.06,5474.12 ; -467.85,4543.27 -467.85,5567.2 ; -98.22,4543.27 -98.22,5567.2 ; 587.79,4543.27 587.79,5567.2 ; 907.46,4543.27 907.46,5567.2 ; 1368.57,4543.27 1368.57,5567.2 ; 2302.73,4543.27 2302.73,5567.2 ; 2674.51,4543.27 2674.51,5567.2 ; 3143.06,4543.27 3143.06,5567.2 ; 3891.11,4543.27 3891.11,5567.2 ; 4426.67,4543.27 4426.67,5567.2 ; 5260,4543.27 5260,5567.2 ; 6093.33,4543.27 6093.33,5567.2 ; -815.44,4543.27 6801.06,4543.27 6801.06,5567.2 -815.44,5567.2 -815.44,4543.27
  text "Symbol" at -759.59,5502.04 h44.68
  text "Count" at -439.92,5502.04 h44.68
  text "Hole Size" at -70.29,5502.04 h44.68
  text "Plated" at 615.72,5502.04 h44.68
  text "Hole Type" at 935.38,5502.04 h44.68
  text "Drill Layer Pair" at 1396.5,5502.04 h44.68
  text "Via/Pad" at 2330.65,5502.04 h44.68
  text "Pad Shape" at 2702.43,5502.04 h44.68
  text "Template" at 3170.99,5502.04 h44.68
  text "Description" at 3919.04,5502.04 h44.68
  text "Hole Tolerance (+)" at 4454.59,5502.04 h44.68
  text "Hole Tolerance (-)" at 5287.92,5502.04 h44.68
  text "Hole Length" at 6121.25,5502.04 h44.68
  text "2" at -439.92,5408.96 h37.23
  text "11.81mil (0.300mm)" at -70.29,5408.96 h37.23
  text "PTH" at 615.72,5408.96 h37.23
  text "Slot" at 935.38,5408.96 h37.23
  text "Top Layer - Bottom Layer" at 1396.5,5408.96 h37.23
  text "Pad" at 2330.65,5408.96 h37.23
  text "Rounded" at 2702.43,5408.96 h37.23
  text "r66_185h30_150r100" at 3170.99,5408.96 h37.23
  text "59.06mil (1.500mm)" at 6121.25,5408.96 h37.23
  text "2" at -439.92,5315.87 h37.23
  text "20.00mil (0.508mm)" at -70.29,5315.87 h37.23
  text "PTH" at 615.72,5315.87 h37.23
  text "Round" at 935.38,5315.87 h37.23
  text "Top Layer - Bottom Layer" at 1396.5,5315.87 h37.23
  text "Pad" at 2330.65,5315.87 h37.23
  text "Rounded" at 2702.43,5315.87 h37.23
  text "c81h51" at 3170.99,5315.87 h37.23
  text "-" at 6121.25,5315.87 h37.23
  text "2" at -439.92,5222.79 h37.23
  text "22.00mil (0.559mm)" at -70.29,5222.79 h37.23
  text "PTH" at 615.72,5222.79 h37.23
  text "Round" at 935.38,5222.79 h37.23
  text "Top Layer - Bottom Layer" at 1396.5,5222.79 h37.23
  text "Pad" at 2330.65,5222.79 h37.23
  text "Rounded" at 2702.43,5222.79 h37.23
  text "c102h56" at 3170.99,5222.79 h37.23
  text "-" at 6121.25,5222.79 h37.23
  text "2" at -439.92,5129.7 h37.23
  text "37.40mil (0.950mm)" at -70.29,5129.7 h37.23
  text "PTH" at 615.72,5129.7 h37.23
  text "Slot" at 935.38,5129.7 h37.23
  text "Top Layer - Bottom Layer" at 1396.5,5129.7 h37.23
  text "Pad" at 2330.65,5129.7 h37.23
  text "Rounded" at 2702.43,5129.7 h37.23
  text "r163_229h95_160r100" at 3170.99,5129.7 h37.23
  text "62.99mil (1.600mm)" at 6121.25,5129.7 h37.23
  text "3" at -439.92,5036.62 h37.23
  text "39.17mil (0.995mm)" at -70.29,5036.62 h37.23
  text "NPTH" at 615.72,5036.62 h37.23
  text "Round" at 935.38,5036.62 h37.23
  text "Top Layer - Bottom Layer" at 1396.5,5036.62 h37.23
  text "Pad" at 2330.65,5036.62 h37.23
  text "Rounded" at 2702.43,5036.62 h37.23
  text "c90hn100" at 3170.99,5036.62 h37.23
  text "-" at 6121.25,5036.62 h37.23
  text "6" at -439.92,4943.53 h37.23
  text "25.59mil (0.650mm)" at -70.29,4943.53 h37.23
  text "PTH" at 615.72,4943.53 h37.23
  text "Round" at 935.38,4943.53 h37.23
  text "Top Layer - Bottom Layer" at 1396.5,4943.53 h37.23
  text "Pad" at 2330.65,4943.53 h37.23
  text "Rounded" at 2702.43,4943.53 h37.23
  text "(Mixed)" at 3170.99,4943.53 h37.23
  text "-" at 6121.25,4943.53 h37.23
  text "16" at -439.92,4850.45 h37.23
  text "5.91mil (0.150mm)" at -70.29,4850.45 h37.23
  text "PTH" at 615.72,4850.45 h37.23
  text "Round" at 935.38,4850.45 h37.23
  text "Top Layer - Bottom Layer" at 1396.5,4850.45 h37.23
  text "Via" at 2330.65,4850.45 h37.23
  text "Rounded" at 2702.43,4850.45 h37.23
  text "(Mixed)" at 3170.99,4850.45 h37.23
  text "-" at 6121.25,4850.45 h37.23
  text "83" at -439.92,4757.37 h37.23
  text "8.00mil (0.203mm)" at -70.29,4757.37 h37.23
  text "PTH" at 615.72,4757.37 h37.23
  text "Round" at 935.38,4757.37 h37.23
  text "Top Layer - Bottom Layer" at 1396.5,4757.37 h37.23
  text "Via" at 2330.65,4757.37 h37.23
  text "Rounded" at 2702.43,4757.37 h37.23
  text "(Mixed)" at 3170.99,4757.37 h37.23
  text "-" at 6121.25,4757.37 h37.23
  text "201" at -439.92,4664.28 h37.23
  text "6.00mil (0.152mm)" at -70.29,4664.28 h37.23
  text "PTH" at 615.72,4664.28 h37.23
  text "Round" at 935.38,4664.28 h37.23
  text "Top Layer - Bottom Layer" at 1396.5,4664.28 h37.23
  text "Via" at 2330.65,4664.28 h37.23
  text "Rounded" at 2702.43,4664.28 h37.23
  text "(Mixed)" at 3170.99,4664.28 h37.23
  text "-" at 6121.25,4664.28 h37.23
  text "317 Total" at -439.92,4571.2 h37.23
  text "Slot definitions :" at -759.59,4477.64 h37.23
  text "Routed Path Length" at -113.72,4477.64 h37.23
  text "= Calculated from tool start centre position to tool end centre position." at 575.58,4477.64 h37.23
  text "Hole Length" at -113.72,4412.01 h37.23
  text "= Routed Path Length + Tool Size = Slot length as defined in the PCB layout" at 321.23,4412.01 h37.23
Mechanical 31:
  drawing of 5167 lines, arcs and shapes, not listed
  text "Sharp corners required here" at 1323.5,1211 h50
  text "Layer Stack Up Detail for: MAX32630 Micro Board" at 1725,478.93 h20
  text "Layer" at 1725,449.35 h11
  text "Name" at 1725,427.35 h11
